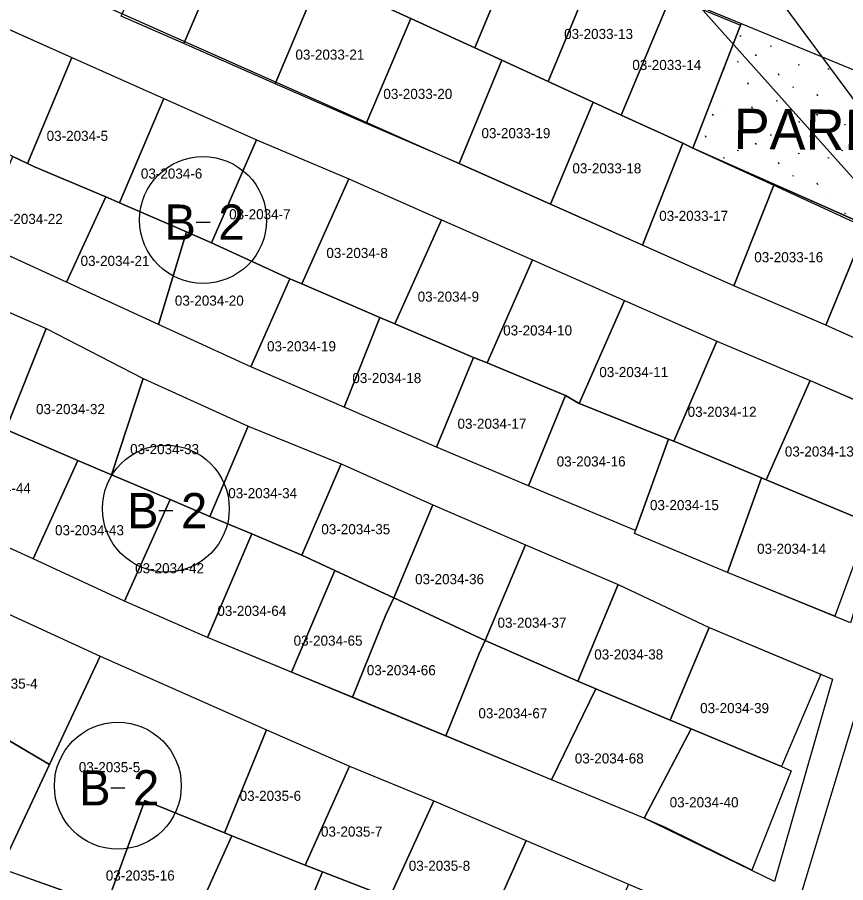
# Model space of a CAD drawing. Extents: x 413946 to 415528, y 4453939 to 4454944.
# Drawn here: x 414198.6 to 414280.9, y 4454485.9 to 4454571.8 of the extents above; entities that cross this region are included whole.
import ezdxf

# ---------------------------------------------------------------- set-up
doc = ezdxf.new("R2010")
doc.units = 0
for name, color, linetype in [('0_KADASTRO', 7, 'Continuous'), ('HAT_ENERJI_NAKIL_HAT', 7, 'Continuous'), ('KST_ENERJI_NAKIL_HAT', 7, 'Continuous'), ('Level 27', 7, 'Continuous'), ('Level 28', 7, 'Continuous'), ('Level 33', 7, 'Continuous'), ('Level 41', 7, 'Continuous'), ('Level 54', 7, 'Continuous'), ('Level 62', 7, 'Continuous'), ('SEMBOL', 7, 'Continuous'), ('SNR_FONKSIYON', 7, 'Continuous')]:
    doc.layers.add(name, color=color, linetype=linetype)

msp = doc.modelspace()

# ---------------------------------------------------------------- linework, layer by layer
at = {"layer": '0_KADASTRO'}
for points in [[(414235.88, 4454572.51), (414240.47, 4454583.54), (414248.76, 4454580.06), (414244.06, 4454568.75), (414237.69, 4454571.68)], [(414208.95, 4454571.89), (414213.73, 4454582.68), (414219.53, 4454580.02), (414219.77, 4454579.91), (414215.18, 4454569.17)], [(414244.06, 4454568.75), (414248.76, 4454580.06), (414256.14, 4454576.98), (414251.32, 4454565.42), (414246.73, 4454567.53)], [(414215.18, 4454569.17), (414219.77, 4454579.91), (414227.71, 4454576.26), (414228.71, 4454575.8), (414224.25, 4454565.19)], [(414251.32, 4454565.42), (414256.14, 4454576.98), (414263.51, 4454573.89), (414258.59, 4454562.08), (414255.79, 4454563.37)], [(414224.25, 4454565.19), (414228.71, 4454575.8), (414235.88, 4454572.51), (414237.69, 4454571.68), (414233.28, 4454561.23)], [(414258.59, 4454562.08), (414263.51, 4454573.89), (414270.43, 4454571), (414265.71, 4454558.81), (414264.71, 4454559.28)], [(414190.69, 4454561.58), (414195.38, 4454571.16), (414195.58, 4454571.57), (414204.05, 4454567.79), (414199.66, 4454557.27), (414198.21, 4454557.96)], [(414233.28, 4454561.23), (414237.69, 4454571.68), (414244.06, 4454568.75), (414246.73, 4454567.53), (414242.51, 4454557.28)], [(414199.66, 4454557.27), (414204.05, 4454567.79), (414213.18, 4454563.73), (414208.8, 4454553.36), (414207.43, 4454553.95), (414200.35, 4454556.94)], [(414242.51, 4454557.28), (414246.73, 4454567.53), (414251.32, 4454565.42), (414255.79, 4454563.37), (414251.58, 4454553.24)], [(414208.8, 4454553.36), (414213.18, 4454563.73), (414222.37, 4454559.64), (414217.91, 4454549.41), (414215.45, 4454550.48)], [(414251.58, 4454553.24), (414255.79, 4454563.37), (414258.59, 4454562.08), (414264.71, 4454559.28), (414260.69, 4454549.18)], [(414217.91, 4454549.41), (414222.37, 4454559.64), (414231.54, 4454555.74), (414226.88, 4454545.32), (414225.69, 4454545.83)], [(414260.69, 4454549.18), (414264.71, 4454559.28), (414265.71, 4454558.81), (414273.74, 4454555.12), (414269.78, 4454545.14)], [(414194.69, 4454549.53), (414198.21, 4454557.96), (414199.66, 4454557.27), (414200.35, 4454556.94), (414207.43, 4454553.95), (414203.51, 4454545.49)], [(414226.88, 4454545.32), (414231.54, 4454555.74), (414240.74, 4454551.69), (414236.11, 4454541.37), (414234.64, 4454541.99)], [(414269.78, 4454545.14), (414273.74, 4454555.12), (414282.87, 4454550.93), (414282.76, 4454550.67), (414278.88, 4454541.23)], [(414203.51, 4454545.49), (414207.43, 4454553.95), (414208.8, 4454553.36), (414215.45, 4454550.48), (414212.64, 4454541.31)], [(414236.11, 4454541.37), (414240.74, 4454551.69), (414249.78, 4454547.7), (414245.28, 4454537.48), (414243.93, 4454538.01)], [(414278.88, 4454541.23), (414282.76, 4454550.67), (414282.87, 4454550.93), (414286.91, 4454549.07), (414291.86, 4454546.81), (414290.51, 4454543.39), (414288.04, 4454537.14)], [(414212.64, 4454541.31), (414215.45, 4454550.48), (414217.91, 4454549.41), (414225.69, 4454545.83), (414221.83, 4454537.09)], [(414245.28, 4454537.48), (414249.78, 4454547.7), (414258.92, 4454543.67), (414254.4, 4454533.44), (414253.07, 4454534.25)], [(414221.83, 4454537.09), (414225.69, 4454545.83), (414226.88, 4454545.32), (414234.64, 4454541.99), (414231.1, 4454533.09)], [(414188.38, 4454535.27), (414192.32, 4454544.9), (414201.52, 4454540.89), (414197.49, 4454530.87), (414195.49, 4454531.83)], [(414254.4, 4454533.44), (414258.92, 4454543.67), (414268.07, 4454539.64), (414263.81, 4454529.71), (414263.29, 4454529.92)], [(414231.1, 4454533.09), (414234.64, 4454541.99), (414236.11, 4454541.37), (414243.93, 4454538.01), (414240.24, 4454529.13)], [(414197.49, 4454530.87), (414201.52, 4454540.89), (414211.13, 4454535.92), (414207.98, 4454526.39), (414204.66, 4454527.81)], [(414263.81, 4454529.71), (414268.07, 4454539.64), (414277.34, 4454535.75), (414272.97, 4454525.89), (414272.5, 4454526.06)], [(414240.24, 4454529.13), (414243.93, 4454538.01), (414245.28, 4454537.48), (414253.07, 4454534.25), (414249.37, 4454525.29)], [(414207.98, 4454526.39), (414211.13, 4454535.92), (414221.57, 4454531.22), (414217.76, 4454522.25), (414213.8, 4454523.93)], [(414272.97, 4454525.89), (414277.34, 4454535.75), (414286.58, 4454531.72), (414283.2, 4454521.62)], [(414249.37, 4454525.29), (414253.07, 4454534.25), (414254.4, 4454533.44), (414263.29, 4454529.92), (414260, 4454520.84)], [(414191.05, 4454522.19), (414195.49, 4454531.83), (414197.49, 4454530.87), (414204.66, 4454527.81), (414200.22, 4454518.05)], [(414217.76, 4454522.25), (414221.57, 4454531.22), (414230.79, 4454527.47), (414226.89, 4454518.4), (414221.91, 4454520.51)], [(414259.9, 4454520.54), (414260, 4454520.84), (414263.29, 4454529.92), (414263.81, 4454529.71), (414272.5, 4454526.06), (414269.13, 4454516.67)], [(414200.22, 4454518.05), (414204.66, 4454527.81), (414207.98, 4454526.39), (414213.8, 4454523.93), (414209.29, 4454513.84)], [(414226.89, 4454518.4), (414230.79, 4454527.47), (414239.88, 4454523.39), (414236.01, 4454514.15), (414230.15, 4454516.881)], [(414269.13, 4454516.67), (414272.5, 4454526.06), (414272.97, 4454525.89), (414283.2, 4454521.62), (414279.78, 4454512.33)], [(414209.29, 4454513.84), (414213.8, 4454523.93), (414217.76, 4454522.25), (414221.91, 4454520.51), (414217.53, 4454510.24)], [(414236.01, 4454514.15), (414239.88, 4454523.39), (414249.08, 4454519.41), (414245.08, 4454509.92)], [(414217.53, 4454510.24), (414221.91, 4454520.51), (414226.89, 4454518.4), (414230.15, 4454516.881), (414225.85, 4454506.799)], [(414245.08, 4454509.92), (414249.08, 4454519.41), (414258.27, 4454515.49), (414254.27, 4454505.9)], [(414225.85, 4454506.799), (414230.15, 4454516.881), (414236.01, 4454514.15), (414235.22, 4454512.47), (414231.899, 4454504.297)], [(414254.27, 4454505.9), (414258.27, 4454515.49), (414267.32, 4454511.22), (414263.44, 4454502.04), (414256.071, 4454505.142)], [(414231.899, 4454504.297), (414235.22, 4454512.47), (414236.01, 4454514.15), (414245.08, 4454509.92), (414244.5, 4454508.65), (414241.162, 4454500.465)], [(414193.22, 4454502.68), (414197.81, 4454512.55), (414206.88, 4454508.38), (414201.83, 4454497.63)], [(414263.44, 4454502.04), (414267.32, 4454511.22), (414278.39, 4454506.6), (414274.5, 4454497.41), (414265.53, 4454501.15)], [(414241.162, 4454500.465), (414244.5, 4454508.65), (414245.08, 4454509.92), (414254.27, 4454505.9), (414256.071, 4454505.142), (414251.678, 4454496.116)], [(414197.01, 4454487.29), (414201.83, 4454497.63), (414206.88, 4454508.38), (414223.39, 4454501.07), (414219.22, 4454490.84), (414211.31, 4454494.05), (414207.45, 4454483.59)], [(414251.678, 4454496.116), (414256.071, 4454505.142), (414263.44, 4454502.04), (414265.53, 4454501.15), (414260.88, 4454492.31)], [(414188.22, 4454491.15), (414193.22, 4454502.68), (414201.83, 4454497.63), (414197.01, 4454487.29)], [(414219.22, 4454490.84), (414223.39, 4454501.07), (414231.63, 4454497.46), (414227.21, 4454487.62), (414219.95, 4454490.54)], [(414260.88, 4454492.31), (414265.53, 4454501.15), (414274.5, 4454497.41), (414275.46, 4454497), (414271.54, 4454487.13), (414262.97, 4454491.37)], [(414227.21, 4454487.62), (414231.63, 4454497.46), (414239.98, 4454494.01), (414235.58, 4454484.39), (414228.92, 4454486.96)], [(414207.45, 4454483.59), (414211.31, 4454494.05), (414219.22, 4454490.84), (414219.95, 4454490.54), (414215.31, 4454480.3)], [(414235.58, 4454484.39), (414239.98, 4454494.01), (414249.14, 4454490.09), (414244.91, 4454480.58), (414238.94, 4454482.94), (414238.48, 4454483.13)], [(414215.31, 4454480.3), (414219.95, 4454490.54), (414227.21, 4454487.62), (414228.92, 4454486.96), (414224.29, 4454475.87), (414224.19, 4454475.64)], [(414244.91, 4454480.58), (414249.14, 4454490.09), (414259.31, 4454485.76), (414255.24, 4454476.29), (414250.32, 4454478.37), (414247.93, 4454479.26)], [(414224.29, 4454475.87), (414228.92, 4454486.96), (414235.58, 4454484.39), (414238.48, 4454483.13), (414233.86, 4454472.72), (414233.55, 4454471.98)]]:
    msp.add_lwpolyline(points, close=True, dxfattribs=at)
at = {"layer": 'HAT_ENERJI_NAKIL_HAT'}
msp.add_lwpolyline([(414658.516, 4453939.478), (414647.224, 4454070.234), (413999.883, 4454943.957)], dxfattribs=at)
at = {"layer": 'KST_ENERJI_NAKIL_HAT'}
msp.add_line((414282.639, 4454554.651), (414232.696, 4454610.603), dxfattribs=at)
at = {"layer": 'Level 27'}
for p, q in [((414269.78, 4454545.14), (414193.078, 4454579.23)), ((414195.58, 4454571.57), (414204.05, 4454567.79)), ((414204.05, 4454567.79), (414213.18, 4454563.73)), ((414213.18, 4454563.73), (414222.37, 4454559.64)), ((414222.37, 4454559.64), (414231.54, 4454555.74)), ((414231.54, 4454555.74), (414240.74, 4454551.69)), ((414240.74, 4454551.69), (414249.78, 4454547.7)), ((414203.51, 4454545.49), (414194.69, 4454549.53)), ((414249.78, 4454547.7), (414258.92, 4454543.67)), ((414192.32, 4454544.9), (414201.52, 4454540.89)), ((414212.64, 4454541.31), (414203.51, 4454545.49)), ((414278.88, 4454541.23), (414269.78, 4454545.14)), ((414258.92, 4454543.67), (414268.07, 4454539.64)), ((414201.52, 4454540.89), (414211.13, 4454535.92)), ((414221.83, 4454537.09), (414212.64, 4454541.31)), ((414288.869, 4454536.77), (414278.88, 4454541.23)), ((414268.07, 4454539.64), (414277.34, 4454535.75)), ((414231.1, 4454533.09), (414221.83, 4454537.09)), ((414211.13, 4454535.92), (414221.57, 4454531.22)), ((414277.34, 4454535.75), (414287.387, 4454531.368)), ((414240.24, 4454529.13), (414231.1, 4454533.09)), ((414221.57, 4454531.22), (414230.79, 4454527.47)), ((414249.37, 4454525.29), (414240.24, 4454529.13)), ((414230.79, 4454527.47), (414239.88, 4454523.39)), ((414260, 4454520.84), (414249.37, 4454525.29)), ((414239.88, 4454523.39), (414249.08, 4454519.41)), ((414200.22, 4454518.05), (414191.05, 4454522.19)), ((414259.9, 4454520.54), (414260, 4454520.84)), ((414269.13, 4454516.67), (414259.9, 4454520.54)), ((414249.08, 4454519.41), (414258.27, 4454515.49)), ((414209.29, 4454513.84), (414200.22, 4454518.05)), ((414281.361, 4454511.686), (414269.13, 4454516.67)), ((414258.27, 4454515.49), (414267.32, 4454511.22)), ((414217.53, 4454510.24), (414209.29, 4454513.84)), ((414197.81, 4454512.55), (414206.88, 4454508.38)), ((414267.32, 4454511.22), (414279.572, 4454506.106)), ((414260.88, 4454492.31), (414217.53, 4454510.24)), ((414206.88, 4454508.38), (414223.39, 4454501.07)), ((414223.39, 4454501.07), (414231.63, 4454497.46)), ((414231.63, 4454497.46), (414239.98, 4454494.01)), ((414239.98, 4454494.01), (414249.14, 4454490.09)), ((414273.814, 4454486.025), (414260.88, 4454492.31)), ((414249.14, 4454490.09), (414259.31, 4454485.76)), ((414207.45, 4454483.59), (414197.01, 4454487.29))]:
    msp.add_line(p, q, dxfattribs=at)
at = {"layer": 'Level 28'}
for p, q in [((414240.47, 4454583.54), (414270.493, 4454571.163)), ((414270.493, 4454571.163), (414295.525, 4454560.843)), ((414279.572, 4454506.106), (414273.814, 4454486.025))]:
    msp.add_line(p, q, dxfattribs=at)
at = {"layer": 'Level 41'}
for p, q in [((414270.368, 4454569.962), (414270.494, 4454569.939)), ((414270.368, 4454569.962), (414270.494, 4454569.939)), ((414273.367, 4454568.938), (414273.492, 4454568.914)), ((414273.367, 4454568.938), (414273.492, 4454568.914)), ((414271.892, 4454568.1), (414272.019, 4454568.001)), ((414271.892, 4454568.1), (414272.019, 4454568.001)), ((414270.098, 4454567.395), (414270.224, 4454567.371)), ((414270.098, 4454567.395), (414270.224, 4454567.371)), ((414268.755, 4454566.674), (414268.848, 4454566.656)), ((414268.755, 4454566.674), (414268.848, 4454566.656)), ((414276.161, 4454567.091), (414276.287, 4454567.067)), ((414276.161, 4454567.091), (414276.287, 4454567.067)), ((414279.09, 4454566.681), (414279.216, 4454566.656)), ((414279.09, 4454566.681), (414279.216, 4454566.656)), ((414274.257, 4454566.022), (414274.191, 4454566.184)), ((414274.257, 4454566.022), (414274.191, 4454566.184)), ((414271.226, 4454565.107), (414271.161, 4454565.27)), ((414271.226, 4454565.107), (414271.161, 4454565.27)), ((414275.576, 4454564.886), (414275.702, 4454564.863)), ((414275.576, 4454564.886), (414275.702, 4454564.863)), ((414267.731, 4454563.958), (414267.717, 4454563.993)), ((414267.731, 4454563.958), (414267.717, 4454563.993)), ((414278.099, 4454563.958), (414278.035, 4454564.119)), ((414278.099, 4454563.958), (414278.035, 4454564.119)), ((414269.088, 4454562.994), (414269.097, 4454562.992)), ((414269.088, 4454562.994), (414269.097, 4454562.992)), ((414271.608, 4454562.725), (414271.543, 4454562.887)), ((414271.608, 4454562.725), (414271.543, 4454562.887)), ((414273.972, 4454563.519), (414274.099, 4454563.495)), ((414273.972, 4454563.519), (414274.099, 4454563.495)), ((414279.456, 4454562.994), (414279.465, 4454562.992)), ((414279.456, 4454562.994), (414279.465, 4454562.992)), ((414267.613, 4454562.155), (414267.74, 4454562.057)), ((414267.613, 4454562.155), (414267.74, 4454562.057)), ((414277.981, 4454562.155), (414278.108, 4454562.057)), ((414277.981, 4454562.155), (414278.108, 4454562.057)), ((414270.368, 4454561.156), (414270.494, 4454561.133)), ((414270.368, 4454561.156), (414270.494, 4454561.133)), ((414276.188, 4454561.451), (414276.314, 4454561.426)), ((414276.188, 4454561.451), (414276.314, 4454561.426)), ((414280.736, 4454561.156), (414280.862, 4454561.133)), ((414280.736, 4454561.156), (414280.862, 4454561.133)), ((414267.033, 4454559.853), (414266.968, 4454560.015)), ((414267.033, 4454559.853), (414266.968, 4454560.015)), ((414273.367, 4454560.132), (414273.492, 4454560.108)), ((414273.367, 4454560.132), (414273.492, 4454560.108)), ((414277.401, 4454559.853), (414277.336, 4454560.015)), ((414277.401, 4454559.853), (414277.336, 4454560.015)), ((414270.098, 4454558.589), (414270.224, 4454558.565)), ((414270.098, 4454558.589), (414270.224, 4454558.565)), ((414271.892, 4454559.294), (414272.019, 4454559.195)), ((414271.892, 4454559.294), (414272.019, 4454559.195)), ((414280.466, 4454558.589), (414280.592, 4454558.565)), ((414280.466, 4454558.589), (414280.592, 4454558.565)), ((414268.722, 4454557.875), (414268.848, 4454557.85)), ((414268.722, 4454557.875), (414268.848, 4454557.85)), ((414276.161, 4454558.285), (414276.287, 4454558.261)), ((414276.161, 4454558.285), (414276.287, 4454558.261)), ((414279.09, 4454557.875), (414279.216, 4454557.85)), ((414279.09, 4454557.875), (414279.216, 4454557.85)), ((414274.257, 4454557.216), (414274.191, 4454557.378)), ((414274.257, 4454557.216), (414274.191, 4454557.378)), ((414271.198, 4454556.372), (414271.161, 4454556.464)), ((414271.198, 4454556.372), (414271.161, 4454556.464)), ((414275.576, 4454556.08), (414275.702, 4454556.057)), ((414275.576, 4454556.08), (414275.702, 4454556.057)), ((414278.099, 4454555.152), (414278.035, 4454555.313)), ((414278.099, 4454555.152), (414278.035, 4454555.313)), ((414279.456, 4454554.188), (414279.465, 4454554.186)), ((414279.456, 4454554.188), (414279.465, 4454554.186)), ((414280.736, 4454552.35), (414280.862, 4454552.327)), ((414280.736, 4454552.35), (414280.862, 4454552.327))]:
    msp.add_line(p, q, dxfattribs=at)
at = {"layer": 'Level 54'}
for points in [[(414197.13, 4454601.67), (414206.35, 4454597.81), (414215.57, 4454593.95), (414223.86, 4454590.48), (414232.17, 4454587.01), (414240.47, 4454583.54), (414270.493, 4454571.163), (414265.71, 4454558.81), (414291.656, 4454547.282), (414288.869, 4454536.77), (414278.88, 4454541.23), (414269.78, 4454545.14), (414193.078, 4454579.23)], [(414195.58, 4454571.57), (414204.05, 4454567.79), (414213.18, 4454563.73), (414222.37, 4454559.64), (414231.54, 4454555.74), (414240.74, 4454551.69), (414249.78, 4454547.7), (414258.92, 4454543.67), (414268.07, 4454539.64), (414277.34, 4454535.75), (414287.387, 4454531.368), (414281.361, 4454511.686), (414269.13, 4454516.67), (414259.9, 4454520.54), (414260, 4454520.84), (414249.37, 4454525.29), (414240.24, 4454529.13), (414231.1, 4454533.09), (414221.83, 4454537.09), (414212.64, 4454541.31), (414203.51, 4454545.49), (414194.69, 4454549.53)], [(414192.32, 4454544.9), (414201.52, 4454540.89), (414211.13, 4454535.92), (414221.57, 4454531.22), (414230.79, 4454527.47), (414239.88, 4454523.39), (414249.08, 4454519.41), (414258.27, 4454515.49), (414267.32, 4454511.22), (414279.572, 4454506.106), (414279.572, 4454506.106), (414273.814, 4454486.025), (414260.88, 4454492.31), (414217.53, 4454510.24), (414209.29, 4454513.84), (414200.22, 4454518.05), (414191.05, 4454522.19)], [(414197.81, 4454512.55), (414206.88, 4454508.38), (414223.39, 4454501.07), (414231.63, 4454497.46), (414239.98, 4454494.01), (414249.14, 4454490.09), (414259.31, 4454485.76), (414271.965, 4454480.343), (414265.908, 4454460.802), (414252.94, 4454465.86), (414243.6, 4454469.26), (414243.53, 4454469.08), (414233.86, 4454472.72), (414233.55, 4454471.98), (414224.29, 4454475.87), (414224.19, 4454475.64), (414215.31, 4454480.3), (414207.45, 4454483.59), (414197.01, 4454487.29)]]:
    msp.add_lwpolyline(points, dxfattribs=at)
at = {"layer": 'Level 62'}
msp.add_lwpolyline([(414306.536, 4454592.896), (414290.275, 4454530.555), (414274.865, 4454479.568), (414264.669, 4454435.816)], dxfattribs=at)
at = {"layer": 'SEMBOL'}
for p, q in [((414216.386, 4454551.457), (414217.786, 4454551.457)), ((414212.686, 4454522.818), (414214.086, 4454522.818)), ((414207.92, 4454495.305), (414209.32, 4454495.305))]:
    msp.add_line(p, q, dxfattribs=at)
for centre in [(414217.086, 4454551.665), (414213.386, 4454523.026), (414208.62, 4454495.513)]:
    msp.add_circle(centre, 6.3, dxfattribs=at)
at = {"layer": 'SNR_FONKSIYON'}
for p, q in [((414265.71, 4454558.81), (414270.493, 4454571.163)), ((414291.656, 4454547.282), (414265.71, 4454558.81))]:
    msp.add_line(p, q, dxfattribs=at)

# ---------------------------------------------------------------- texts
at = {"layer": '0_KADASTRO'}
for s, p in [('03-2033-13', (414252.919, 4454569.632)), ('03-2033-21', (414226.248, 4454567.581)), ('03-2033-14', (414259.689, 4454566.555)), ('03-2033-20', (414234.976, 4454563.683)), ('03-2034-5', (414201.554, 4454559.519)), ('03-2033-19', (414244.713, 4454559.784)), ('03-2033-18', (414253.74, 4454556.297)), ('03-2034-6', (414210.908, 4454555.775)), ('03-2034-7', (414219.671, 4454551.736)), ('03-2033-17', (414262.356, 4454551.578)), ('03-2034-22', (414196.312, 4454551.273)), ('03-2034-8', (414229.321, 4454547.895)), ('03-2033-16', (414271.794, 4454547.475)), ('03-2034-21', (414204.921, 4454547.107)), ('03-2034-20', (414214.28, 4454543.166)), ('03-2034-9', (414238.38, 4454543.56)), ('03-2034-10', (414246.867, 4454540.21)), ('03-2034-19', (414223.432, 4454538.634)), ('03-2034-11', (414256.413, 4454536.072)), ('03-2034-18', (414231.9, 4454535.481)), ('03-2034-32', (414200.5, 4454532.4)), ('03-2034-12', (414265.18, 4454532.131)), ('03-2034-17', (414242.337, 4454530.949)), ('03-2034-33', (414209.84, 4454528.426)), ('03-2034-13', (414274.83, 4454528.19)), ('03-2034-16', (414252.183, 4454527.205)), ('03-2034-44', (414193.145, 4454524.55)), ('03-2034-34', (414219.578, 4454524.054)), ('03-2034-15', (414261.439, 4454522.87)), ('03-2034-43', (414202.386, 4454520.377)), ('03-2034-35', (414228.819, 4454520.476)), ('03-2034-14', (414272.073, 4454518.535)), ('03-2034-42', (414210.337, 4454516.601)), ('03-2034-36', (414238.127, 4454515.521)), ('03-2034-64', (414218.5, 4454512.373)), ('03-2034-37', (414246.308, 4454511.198)), ('03-2034-65', (414226.067, 4454509.416)), ('03-2034-38', (414255.912, 4454508.049)), ('03-2034-66', (414233.335, 4454506.482)), ('03-2035-4', (414194.563, 4454505.152)), ('03-2034-39', (414266.42, 4454502.723)), ('03-2034-67', (414244.41, 4454502.212)), ('03-2034-68', (414253.979, 4454497.729)), ('03-2035-5', (414204.745, 4454496.861)), ('03-2035-6', (414220.712, 4454494.015)), ('03-2034-40', (414263.393, 4454493.373)), ('03-2035-7', (414228.783, 4454490.464)), ('03-2035-8', (414237.499, 4454487.074)), ('03-2035-16', (414207.424, 4454486.106))]:
    msp.add_text(s, height=1, dxfattribs=at).set_placement(p)
at = {"layer": 'Level 33'}
msp.add_text('PARK', height=4, rotation=359.4136, dxfattribs=at).set_placement((414269.737, 4454558.725))
at = {"layer": 'SEMBOL'}
for s, p in [('B', (414213.241, 4454549.707)), ('2', (414218.594, 4454549.707)), ('B', (414209.541, 4454521.068)), ('2', (414214.894, 4454521.068)), ('B', (414204.775, 4454493.555)), ('2', (414210.127, 4454493.555))]:
    msp.add_text(s, height=3.5, dxfattribs=at).set_placement(p)

doc.saveas('drawing.dxf')
